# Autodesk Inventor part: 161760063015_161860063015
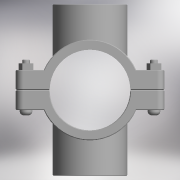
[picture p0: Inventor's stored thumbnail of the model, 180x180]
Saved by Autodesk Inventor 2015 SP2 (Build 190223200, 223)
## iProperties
Created: 2017-05
Part Number: 161760063015_161860063015
Material: Generic
Description: PLASSON DOUBLE SADDLE 63-1.1/2"
Document SubType Name: Modeling
Designer: KIM
Density: 1 g/cm^3
Appearance: Default
Author: KIM
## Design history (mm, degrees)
derived "16176.ipt"
feature "Solid1::16176.ipt"
feature "Solid2::16176.ipt"
tag "TaggingFeature1"
body "Solid1"
body "Solid2"
other parameters: "d0" = 78.75, "d1" = 116, "d2" = 31.5, "d3" = 63, "d4" = 84, "d5" = 0, "d6" = 5.8, "d7" = 116, "d8" = 0.1, "d10" = 0, "d11" = 0.63, "d20" = 0.63, "d23" = 0.63, "d37" = 8, "d38" = 39.5, "d39" = 0, "d40" = 3, "d41" = 5, "d42" = 0, "d43" = 6, "d44" = 3, "d45" = 0, "d46" = 0.63, "d52" = 44.845, "d53" = 25, "d54" = 0, "d55" = 39, "d57" = 0, "d58" = 68.04, "d60" = 0, "d63" = 8, "d66" = 68, "d67" = 134, "d68" = 58.2985, "d69" = 44.845, "d70" = 25, "d71" = 0, "d72" = 39, "d74" = 0, "d75" = 0.63, "d_" = 63, "B_" = 39, "G_" = 44.845, "A_" = 67, "L_" = 116, "L_1" = 84, "l_2" = 25
